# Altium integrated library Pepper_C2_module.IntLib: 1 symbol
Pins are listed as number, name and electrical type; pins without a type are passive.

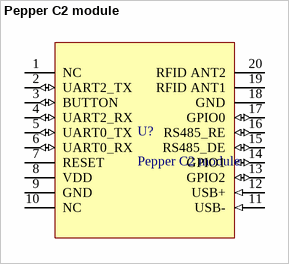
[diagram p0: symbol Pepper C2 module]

## Pepper C2 module
designator U?
Pepper C2 FCC Approved RFID module; Manufacturer: Eccel Technology Ltd; Manufacturer P/N: 000691
footprint Pepper_C2R
pins: 1 NC (power), 2 UART2_TX (io), 3 BUTTON (io), 4 UART2_RX (io), 5 UART0_TX (io), 6 UART0_RX (io), 7 RESET, 8 VDD (power), 9 GND (power), 10 NC, 11 USB- (in), 12 USB+ (in), 13 GPIO2 (io), 14 GPIO1 (io), 15 RS485_DE (io), 16 RS485_RE (io), 17 GPIO0 (io), 18 GND, 19 RFID ANT1, 20 RFID ANT2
